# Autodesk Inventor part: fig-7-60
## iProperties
Shininess: 64.0
Length Units: 11269
Angle Units: 11279
Time Units: 11290
Mass Units: 11283
Length Display Precision: 3
Angle Display Precision: 2
Compacted: True
Part Number: fig-7-60
Document SubType Name: Modeling
Created: 2003-08
Designer: Owner
Manufacturer: Standard
Standards Organization: Custom
Density: 1 g/cm^3
Density: 0.0
Volumn: 0.0
Area: 0.0
PropertySet Name: Model Information
Control State: 0
Master: False
Checked Out: False
Author: Owner
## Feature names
1. Split6
